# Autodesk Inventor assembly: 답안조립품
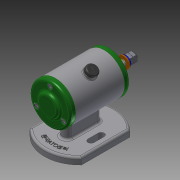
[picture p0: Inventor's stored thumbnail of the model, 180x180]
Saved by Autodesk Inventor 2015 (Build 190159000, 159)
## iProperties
Created: 2022-02
Part Number: 답안조립품
Document SubType Name: Assembly
Designer: pc-04
Author: pc-04
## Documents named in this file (14)
- C:\Users\pc-04\Desktop\720206V1012\답안조립품.iam
- C:\Users\pc-04\Desktop\720206V1012\본체.ipt
- C:\Users\pc-04\Desktop\720206V1012\V벨트풀리.ipt
- C:\Users\pc-04\Desktop\720206V1012\고무 캡.ipt
- C:\Users\pc-04\Desktop\720206V1012\너트 M8.ipt
- C:\Users\pc-04\Desktop\720206V1012\뒤커버.ipt
- C:\Users\pc-04\Desktop\720206V1012\베어링 6002.ipt
- C:\Users\pc-04\Desktop\720206V1012\볼트 M4 x 10.ipt
- C:\Users\pc-04\Desktop\720206V1012\스프링와셔 8.ipt
- C:\Users\pc-04\Desktop\720206V1012\앞커버.ipt
- C:\Users\pc-04\Desktop\720206V1012\오일 실 15 x 25 x 7.ipt
- C:\Users\pc-04\Desktop\720206V1012\축.ipt
- C:\Users\pc-04\Desktop\720206V1012\키 3 x 3 x 12.ipt
- C:\Users\pc-04\Desktop\720206V1012\평와셔 8 x 17.ipt
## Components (2 placed, 2 different names)
1. V벨트풀리:1
2. 고무 캡:1
